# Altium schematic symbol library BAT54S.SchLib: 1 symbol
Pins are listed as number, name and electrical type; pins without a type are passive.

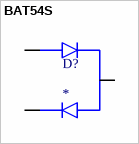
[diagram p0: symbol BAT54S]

## BAT54S
designator D?
SOT-23 30V 0.2A Diodes Rectifi; MF: ON; MP: BAT54S
footprint BAT54S
pins: 1, 2, 3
